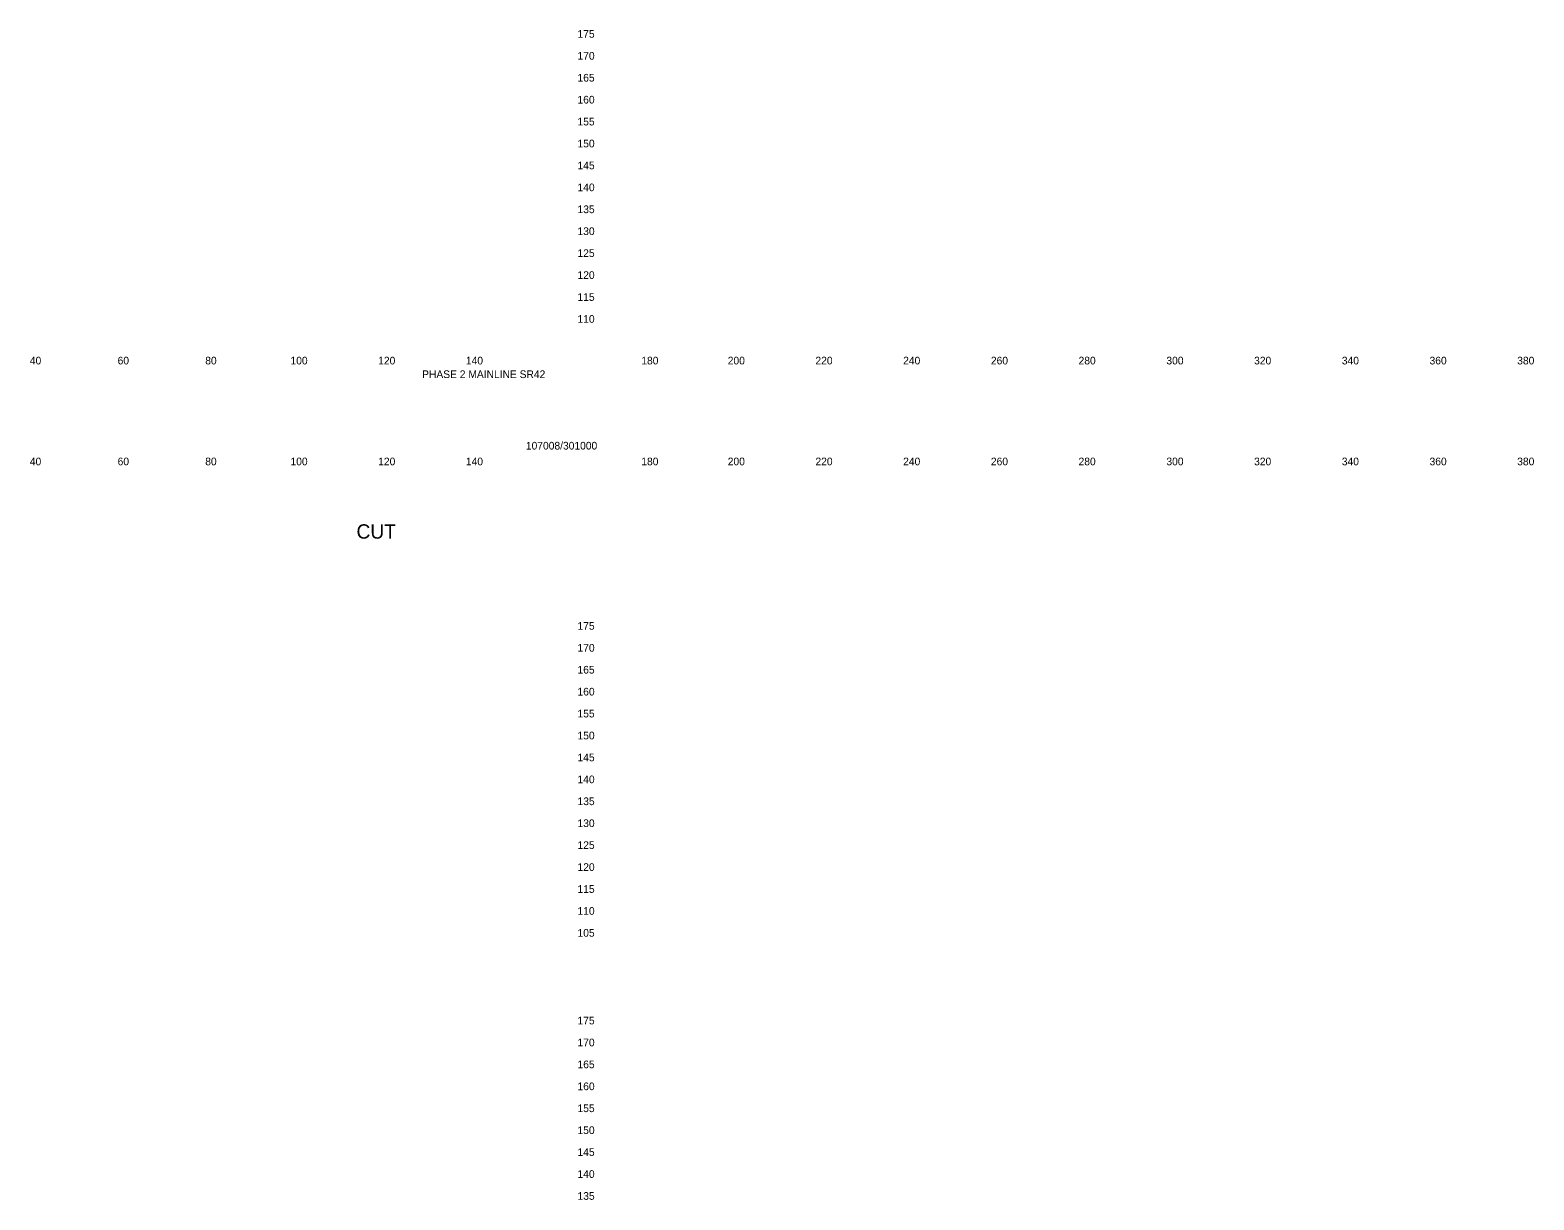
# Model space of a CAD drawing. Extents: x 21281 to 22024, y 6472 to 15208.
# Drawn here: x 21681.3 to 22024.2, y 11114.8 to 11381.6 of the extents above; entities that cross this region are included whole.
import ezdxf

# ---------------------------------------------------------------- set-up
doc = ezdxf.new("R2010")
doc.units = 0
doc.layers.add('XS_SHEET_LABELS_ELEVATION', color=7, linetype='Continuous')
doc.layers.add('XS_SHEET_LABELS_OFFSET', color=7, linetype='Continuous')

msp = doc.modelspace()

# ---------------------------------------------------------------- texts
at = {"layer": 'XS_SHEET_LABELS_ELEVATION'}
for s, p in [('  175  ', (21804.84, 11379.84)), ('  170  ', (21804.84, 11374.84)), ('  165  ', (21804.84, 11369.84)), ('  160  ', (21804.84, 11364.84)), ('  155  ', (21804.84, 11359.84)), ('  150  ', (21804.84, 11354.84)), ('  145  ', (21804.84, 11349.84)), ('  140  ', (21804.84, 11344.84)), ('  135  ', (21804.84, 11339.84)), ('  130  ', (21804.84, 11334.84)), ('  125  ', (21804.84, 11329.84)), ('  120  ', (21804.84, 11324.84)), ('  115  ', (21804.84, 11319.84)), ('  110  ', (21804.84, 11314.84)), ('  175  ', (21804.84, 11244.84)), ('  170  ', (21804.84, 11239.84)), ('  165  ', (21804.84, 11234.84)), ('  160  ', (21804.84, 11229.84)), ('  155  ', (21804.84, 11224.84)), ('  150  ', (21804.84, 11219.84)), ('  145  ', (21804.84, 11214.84)), ('  140  ', (21804.84, 11209.84)), ('  135  ', (21804.84, 11204.84)), ('  130  ', (21804.84, 11199.84)), ('  125  ', (21804.84, 11194.84)), ('  120  ', (21804.84, 11189.84)), ('  115  ', (21804.84, 11184.84)), ('  110  ', (21804.84, 11179.84)), ('  105  ', (21804.84, 11174.84)), ('  175  ', (21804.84, 11154.84)), ('  170  ', (21804.84, 11149.84)), ('  165  ', (21804.84, 11144.84)), ('  160  ', (21804.84, 11139.84)), ('  155  ', (21804.84, 11134.84)), ('  150  ', (21804.84, 11129.84)), ('  145  ', (21804.84, 11124.84)), ('  140  ', (21804.84, 11119.84)), ('  135  ', (21804.84, 11114.84))]:
    msp.add_text(s, height=1.75, dxfattribs=at).set_placement(p)
at = {"layer": 'XS_SHEET_LABELS_OFFSET'}
for s, height, p in [('  40  ', 1.75, (21679.95, 11305.34)), ('  60  ', 1.75, (21699.97, 11305.34)), ('  80  ', 1.75, (21719.95, 11305.34)), ('  100  ', 1.75, (21739.39, 11305.34)), ('  120  ', 1.75, (21759.39, 11305.34)), ('  140  ', 1.75, (21779.39, 11305.34)), ('  180  ', 1.75, (21819.39, 11305.34)), ('  200  ', 1.75, (21839.1, 11305.34)), ('  220  ', 1.75, (21859.1, 11305.34)), ('  240  ', 1.75, (21879.1, 11305.34)), ('  260  ', 1.75, (21899.11, 11305.34)), ('  280  ', 1.75, (21919.1, 11305.34)), ('  300  ', 1.75, (21939.13, 11305.34)), ('  320  ', 1.75, (21959.13, 11305.34)), ('  340  ', 1.75, (21979.13, 11305.34)), ('  360  ', 1.75, (21999.14, 11305.34)), ('  380  ', 1.75, (22019.13, 11305.34)), ('PHASE 2 MAINLINE SR42', 1.75, (21770.71, 11302.23)), ('107008/301000', 1.75, (21794.37, 11285.93)), ('  40  ', 1.75, (21679.95, 11282.34)), ('  60  ', 1.75, (21699.97, 11282.34)), ('  80  ', 1.75, (21719.95, 11282.34)), ('  100  ', 1.75, (21739.39, 11282.34)), ('  120  ', 1.75, (21759.39, 11282.34)), ('  140  ', 1.75, (21779.39, 11282.34)), ('  180  ', 1.75, (21819.39, 11282.34)), ('  200  ', 1.75, (21839.1, 11282.34)), ('  220  ', 1.75, (21859.1, 11282.34)), ('  240  ', 1.75, (21879.1, 11282.34)), ('  260  ', 1.75, (21899.11, 11282.34)), ('  280  ', 1.75, (21919.1, 11282.34)), ('  300  ', 1.75, (21939.13, 11282.34)), ('  320  ', 1.75, (21959.13, 11282.34)), ('  340  ', 1.75, (21979.13, 11282.34)), ('  360  ', 1.75, (21999.14, 11282.34)), ('  380  ', 1.75, (22019.13, 11282.34)), ('CUT', 3.273, (21755.74, 11265.61))]:
    msp.add_text(s, height=height, dxfattribs=at).set_placement(p)

doc.saveas('drawing.dxf')
